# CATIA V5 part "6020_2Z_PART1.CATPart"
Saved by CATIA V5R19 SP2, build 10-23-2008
Part number: 6020_2Z_PART1
Bounding box of the stored display mesh (mm): x 0 to 24, y -58 to 58, z -57.82 to 57.82
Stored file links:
  G:\EU_thinkMotion\CFAO_2010\MMS_groupe2\MMS_groupe2\OK\nrosalie\nrosalie_cfao_support_d_arme_legere_final\6020_2Z_PART1.CATPart
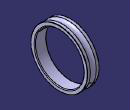
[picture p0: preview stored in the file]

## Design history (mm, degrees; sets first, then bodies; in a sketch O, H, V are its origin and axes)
Set1
  Point1: (0, 0, 0)
  Point2: (1, 0, 0)
  Point3: (0, 1, 0)
  Plane1: type 3Points, Element1 Point1, Element2 Point2, Element3 Point3
Body1 (main body)
  Sketch1 on Plane1, origin (0, 0, 0), H (1, 0, 0), V (0, 1, 0)
    arc A1 centre (1.5, 51.5) radius 1.5 from (0, 51.5) to (1.5, 50) ccw
    point P1 (1.5, 50)
    point P2 (22.5, 50)
    line L1 (1.5, 50) -> (22.5, 50)
    arc A2 centre (22.5, 51.5) radius 1.5 from (22.5, 50) to (24, 51.5) ccw
    point P3 (24, 51.5)
    point P4 (24, 57.5)
    line L2 (24, 51.5) -> (24, 57.5)
    arc A3 centre (23.5, 57.5) radius 0.5 from (24, 57.5) to (23.5, 58) ccw
    point P5 (23.5, 58)
    point P6 (18.0499, 58)
    line L3 (23.5, 58) -> (18.0499, 58)
    arc A4 centre (12, 62.5) radius 7.54 from (5.9501, 58) to (18.0499, 58) ccw
    point P7 (5.9501, 58)
    point P8 (0.5, 58)
    line L4 (5.9501, 58) -> (0.5, 58)
    arc A5 centre (0.5, 57.5) radius 0.5 from (0.5, 58) to (0, 57.5) ccw
    point P9 (0, 57.5)
    point P10 (0, 51.5)
    line L5 (0, 57.5) -> (0, 51.5)
    point P11 (22.5, 0)
    point P12 (1.5, 0)
    axis line L6 (22.5, 0) -> (1.5, 0)
    point P13 (0, 51.5)
    point P14 (1.5, 50)
    point P15 (1.5, 50)
    point P16 (22.5, 50)
    point P17 (22.5, 50)
    point P18 (24, 51.5)
    point P19 (24, 51.5)
    point P20 (24, 57.5)
    point P21 (24, 57.5)
    point P22 (23.5, 58)
    point P23 (23.5, 58)
    point P24 (18.0499, 58)
    point P25 (5.9501, 58)
    point P26 (18.0499, 58)
    point P27 (5.9501, 58)
    point P28 (0.5, 58)
    point P29 (0.5, 58)
    point P30 (0, 57.5)
    point P31 (0, 57.5)
    point P32 (0, 51.5)
    coincidence: P13 P32, P14 P15, P16 P17, P18 P19, P20 P21, P22 P23, P24 P26, P25 P27, P28 P29, P30 P31
  Shaft1: profile Sketch1, axis Sketch1.L6, angle 360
